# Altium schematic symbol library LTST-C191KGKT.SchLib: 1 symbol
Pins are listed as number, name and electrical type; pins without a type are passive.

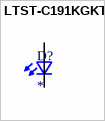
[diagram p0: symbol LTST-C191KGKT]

## LTST-C191KGKT
designator D?
Green 571nm LED Indication - Discrete 2V 0603 (1608 Metric); MF: Lite-On Inc.; MP: LTST-C191KGKT
footprint 0603
pins: 1 K2, 2 A2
